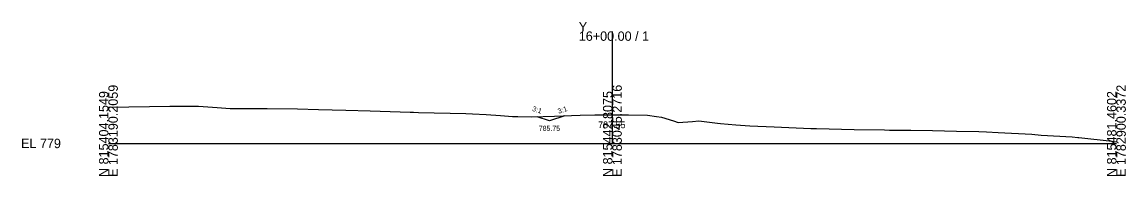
# Model space of a CAD drawing. Extents: x -12583 to 5303, y -44 to 25667.
# Drawn here: x -25.7 to 302.8, y 5490.3 to 5536.2 of the extents above; entities that cross this region are included whole.
import ezdxf

# ---------------------------------------------------------------- set-up
doc = ezdxf.new("R2010")
doc.units = 0
for name, color, linetype in [('Exist Cross Section Cell', 7, 'Continuous'), ('Exist XS Center Line Elevation Label', 7, 'Continuous'), ('Exist XS Ground Line', 7, 'Continuous'), ('Prop XS DDE', 7, 'Continuous'), ('Prop XS Ditch Slope Text', 7, 'Continuous'), ('Prop XS Ditch Standard Text', 7, 'Continuous'), ('Prop XS Side Slope Text', 7, 'Continuous')]:
    doc.layers.add(name, color=color, linetype=linetype)

msp = doc.modelspace()

# ---------------------------------------------------------------- linework, layer by layer
at = {"layer": 'Exist Cross Section Cell'}
for p, q in [((150, 5500), (150, 5533.38)), ((0, 5500), (150, 5500)), ((150, 5500), (300, 5500))]:
    msp.add_line(p, q, dxfattribs=at)
at = {"layer": 'Exist XS Ground Line'}
for p, q in [((0, 5510.83), (18.25, 5511.08)), ((18.25, 5511.08), (21.88, 5511.13)), ((21.88, 5511.13), (24.42, 5511.12)), ((24.42, 5511.12), (26.78, 5511.08)), ((26.78, 5511.08), (32.4, 5510.69)), ((32.4, 5510.69), (36.22, 5510.46)), ((36.22, 5510.46), (37.09, 5510.45)), ((37.09, 5510.45), (39.05, 5510.39)), ((39.05, 5510.39), (42.98, 5510.42)), ((42.98, 5510.42), (47.29, 5510.39)), ((47.29, 5510.39), (56.29, 5510.3)), ((56.29, 5510.3), (62.51, 5510.16)), ((62.51, 5510.16), (70.67, 5509.94)), ((70.67, 5509.94), (77.95, 5509.76)), ((77.95, 5509.76), (89.83, 5509.31)), ((89.83, 5509.31), (90.79, 5509.27)), ((90.79, 5509.27), (92.26, 5509.23)), ((92.26, 5509.23), (106.39, 5508.92)), ((106.39, 5508.92), (108.37, 5508.8)), ((108.37, 5508.8), (112.45, 5508.58)), ((112.45, 5508.58), (116.7, 5508.31)), ((116.7, 5508.31), (120.25, 5508.03)), ((120.25, 5508.03), (121.85, 5508.02)), ((121.85, 5508.02), (125.97, 5507.92)), ((125.97, 5507.92), (132.78, 5508.12)), ((132.78, 5508.12), (140.38, 5508.44)), ((140.38, 5508.44), (144.78, 5508.49)), ((144.78, 5508.49), (150, 5508.55)), ((150, 5508.55), (150.31, 5508.56)), ((150.31, 5508.56), (154.81, 5508.5)), ((154.81, 5508.5), (160.4, 5508.44)), ((160.4, 5508.44), (163.1, 5508)), ((163.1, 5508), (164.62, 5507.79)), ((164.62, 5507.79), (168.19, 5506.7)), ((168.19, 5506.7), (169.53, 5506.24)), ((169.53, 5506.24), (173.84, 5506.55)), ((173.84, 5506.55), (175.73, 5506.7)), ((175.73, 5506.7), (181.27, 5506.04)), ((181.27, 5506.04), (182.2, 5505.91)), ((182.2, 5505.91), (186.77, 5505.54)), ((186.77, 5505.54), (190.93, 5505.24)), ((190.93, 5505.24), (198.12, 5504.95)), ((198.12, 5504.95), (209.06, 5504.46)), ((209.06, 5504.46), (209.65, 5504.44)), ((209.65, 5504.44), (210.71, 5504.41)), ((210.71, 5504.41), (222, 5504.15)), ((222, 5504.15), (230.95, 5504.01)), ((230.95, 5504.01), (232.5, 5504)), ((232.5, 5504), (238.8, 5503.93)), ((238.8, 5503.93), (245.27, 5503.82)), ((245.27, 5503.82), (252.44, 5503.67)), ((252.44, 5503.67), (259.02, 5503.55)), ((259.02, 5503.55), (261.37, 5503.42)), ((261.37, 5503.42), (264.78, 5503.22)), ((264.78, 5503.22), (274.8, 5502.73)), ((274.8, 5502.73), (277.64, 5502.5)), ((277.64, 5502.5), (286.88, 5501.93)), ((286.88, 5501.93), (288.52, 5501.77)), ((288.52, 5501.77), (288.84, 5501.75)), ((288.84, 5501.75), (298.75, 5500.66)), ((298.75, 5500.66), (300, 5500.51))]:
    msp.add_line(p, q, dxfattribs=at)
at = {"layer": 'Prop XS DDE'}
for p, q in [((131.32, 5506.75), (127.66, 5507.97)), ((135.8, 5508.25), (131.32, 5506.75))]:
    msp.add_line(p, q, dxfattribs=at)

# ---------------------------------------------------------------- texts
at = {"layer": 'Exist Cross Section Cell'}
for s, p in [('Y', (140, 5533.38)), ('16+00.00 / 1', (140, 5530.58)), ('EL 779', (-26, 5498.6))]:
    msp.add_text(s, height=2.8, dxfattribs=at).set_placement(p)
for s, p in [('E 1783190.2059', (2.8, 5490)), ('E 1783045.2716', (152.8, 5490)), ('E 1782900.3372', (302.8, 5490)), ('N 815404.1549', (0, 5490)), ('N 815442.8075', (150, 5490)), ('N 815481.4602', (300, 5490))]:
    msp.add_text(s, height=2.8, rotation=90, dxfattribs=at).set_placement(p)
at = {"layer": 'Exist XS Center Line Elevation Label'}
msp.add_text('787.55', height=2, dxfattribs=at).set_placement((145.74, 5504.55))
at = {"layer": 'Prop XS Ditch Slope Text'}
msp.add_text('3:1', height=1.5, rotation=18.4349, dxfattribs=at).set_placement((134, 5508.81))
at = {"layer": 'Prop XS Ditch Standard Text'}
msp.add_text('785.75', height=1.5, dxfattribs=at).set_placement((128.09, 5503.75))
at = {"layer": 'Prop XS Side Slope Text'}
msp.add_text('3:1', height=1.5, rotation=341.5651, dxfattribs=at).set_placement((126, 5509.75))

doc.saveas('drawing.dxf')
